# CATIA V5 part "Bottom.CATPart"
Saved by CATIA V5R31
Part number: Plate
Bounding box of the stored display mesh (mm): x -85 to 85, y -84.802 to 84.802, z 0 to 10
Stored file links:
  D:\PROJECTS\Project 2021\US EDITION\CATIA V5 6R 2021\Resources\Part Files\c12_catia_v5_6r2021_prt\c12_catia_v5-6r2021 figr_12-30\Bottom.CATPart
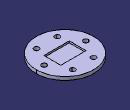
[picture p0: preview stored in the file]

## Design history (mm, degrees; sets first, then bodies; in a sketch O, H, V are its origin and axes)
Body1 (main body)
  Sketch1 on xy-plane, origin (0, 0, 0), H (1, 0, 0), V (0, 1, 0)
    circle A1 centre (0, 0) radius 85
    line L1 (37.5, 25) -> (37.5, -25)
    line L2 (37.5, -25) -> (-37.5, -25)
    line L3 (-37.5, -25) -> (-37.5, 25)
    line L4 (-37.5, 25) -> (37.5, 25)
    length L2 = 75
    length L1 = 50
    radius A1 = 85
    vertical: L1 V, L3 V
    horizontal: L2 H, L4 H
    equidistance: L1 L3 O, L2 L4 O
  MultiPad1: profile Sketch1, domains (length 5; length 10)
  Sketch2 on face of MultiPad1, origin (0, 0, 10), H (1, 0, 0), V (0, 1, 0)
    circle A1 centre (62, 0) radius 7.5
    point P1 (62, 0)
    radius A1 = 7.5
    distance P1 V = 62
    coincidence: P1 H
  Pocket1: profile Sketch2, direction (0, 0, -1), through (limit type 6)
  CircPattern1: of Pocket1, instances 6, angular step 60 {= 360.0*1 deg/CircPattern1.AngularNumber}, axis from xy-plane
